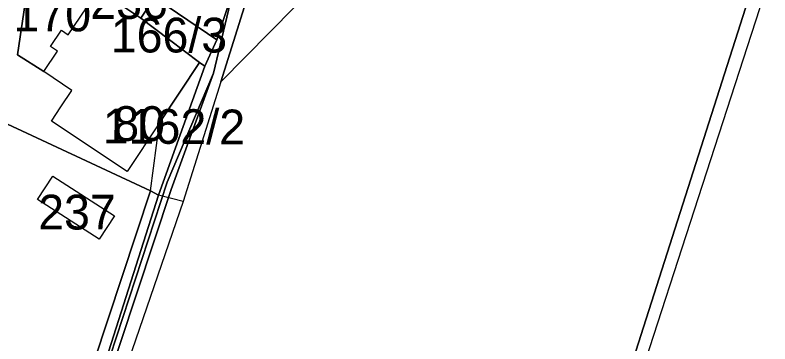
# Model space of a CAD drawing. Extents: x -623250 to -619626, y -1079612 to -1075424.
# Drawn here: x -621418.9 to -621201.9, y -1077758.8 to -1077664.2 of the extents above; entities that cross this region are included whole.
import ezdxf

# ---------------------------------------------------------------- set-up
doc = ezdxf.new("R2010")
doc.units = 0
for name, color, linetype in [('Hranice šetřená (k_ú_Džbánov - vnitřní obvod)', 7, 'Continuous'), ('Parcela nároku', 7, 'Continuous'), ('Parcelní číslo', 7, 'Continuous')]:
    doc.layers.add(name, color=color, linetype=linetype)

msp = doc.modelspace()

# ---------------------------------------------------------------- linework, layer by layer
at = {"layer": 'Hranice šetřená (k_ú_Džbánov - vnitřní obvod)'}
for points in [[(-621379.95, -1077714.81), (-621472.37, -1077671.75), (-621477.29, -1077669.61), (-621474.91, -1077659.48), (-621473.93, -1077656.14), (-621481.28, -1077655.23), (-621493.28, -1077651.08), (-621501.26, -1077644.07), (-621534.26, -1077633.61), (-621575.49, -1077614.16), (-621575.63, -1077614.69), (-621576.66, -1077618.59), (-621578.64, -1077626.08), (-621580.59, -1077633.46), (-621573.12, -1077638.43), (-621578.37, -1077655.91), (-621582.97, -1077675.43), (-621585.55, -1077686.35), (-621591.87, -1077710.12)], [(-621340.28, -1077622.09), (-621346.96, -1077620.27), (-621351.15, -1077650.83), (-621352.43, -1077660.2), (-621359.74, -1077683.39), (-621370.61, -1077717.85), (-621377.7, -1077716.06), (-621379.95, -1077714.81)]]:
    msp.add_lwpolyline(points, dxfattribs=at)
at = {"layer": 'Parcela nároku'}
for points in [[(-621399.07, -1077604.61), (-621366.26, -1077618.67), (-621352.61, -1077624.67), (-621356.07, -1077656.62), (-621360.94, -1077671.33), (-621411.21, -1077637.14)], [(-621287.56, -1077905.65), (-621340.92, -1078060.83), (-621413.47, -1078234.45), (-621461.2, -1078328.4), (-621462.02, -1078334.75), (-621459.02, -1078330.44), (-621410.27, -1078236.51), (-621337.32, -1078062), (-621284.16, -1077906.18), (-621257.6, -1077825.18), (-621204.75, -1077662.32), (-621198.6, -1077626.58), (-621199.7, -1077617.03), (-621206.08, -1077609.32), (-621211.44, -1077608.6), (-621204.6, -1077618.06), (-621201.95, -1077630.34), (-621208.08, -1077659.7), (-621260.76, -1077824.45)], [(-621325.15, -1077626.4), (-621318.07, -1077628.41), (-621297.64, -1077634.23), (-621296.82, -1077634.46), (-621331.45, -1077654.68), (-621359.74, -1077683.39), (-621352.43, -1077660.2), (-621351.15, -1077650.83)], [(-621412.36, -1077639.98), (-621411.21, -1077637.14), (-621360.94, -1077671.33), (-621364.39, -1077678.9), (-621365.89, -1077677.89), (-621374.5, -1077671.38), (-621382.78, -1077665.12), (-621379.74, -1077660.62), (-621391.87, -1077652.44), (-621394.73, -1077656.69), (-621412.76, -1077641.87)], [(-621468.32, -1077652.78), (-621469.02, -1077655.02), (-621472.37, -1077671.75), (-621379.95, -1077714.81), (-621377.39, -1077695.22), (-621386.69, -1077709.23), (-621408.45, -1077694.77), (-621405.71, -1077690.62), (-621402.58, -1077685.89), (-621410.62, -1077680.48), (-621418.22, -1077675.64), (-621414.14, -1077648.39), (-621417.6, -1077642.03), (-621426.47, -1077663.99)], [(-621414.14, -1077648.39), (-621418.22, -1077675.64), (-621410.62, -1077680.48), (-621406.69, -1077674.58), (-621408.69, -1077673.25), (-621405.55, -1077668.55), (-621403.62, -1077669.9), (-621394.73, -1077656.69), (-621412.76, -1077641.87)], [(-621391.87, -1077652.44), (-621379.74, -1077660.62), (-621382.78, -1077665.12), (-621386.75, -1077662.39), (-621394.73, -1077656.69)], [(-621364.39, -1077678.9), (-621360.94, -1077671.33), (-621356.07, -1077656.62), (-621361.81, -1077680.91), (-621375.21, -1077712.24), (-621395.2, -1077773.48), (-621413.63, -1077833.01), (-621448.87, -1077932.09), (-621484.15, -1078031.22), (-621531.47, -1078143.68), (-621559.31, -1078200.97), (-621633.61, -1078348.03), (-621651.3, -1078390.37), (-621666.67, -1078429.48), (-621674.85, -1078456.45), (-621678.32, -1078456.03), (-621652.48, -1078389.36), (-621636.77, -1078350.51), (-621560.48, -1078200.14), (-621532.5, -1078143.13), (-621485.18, -1078030.89), (-621450, -1077931.7), (-621414.98, -1077832.91), (-621377.7, -1077716.06)], [(-621374.5, -1077671.38), (-621365.89, -1077677.89), (-621377.39, -1077695.22), (-621386.69, -1077709.23), (-621408.45, -1077694.77), (-621405.71, -1077690.62), (-621402.58, -1077685.89), (-621410.62, -1077680.48), (-621406.69, -1077674.58), (-621408.69, -1077673.25), (-621405.55, -1077668.55), (-621403.62, -1077669.9), (-621394.73, -1077656.69), (-621386.75, -1077662.39), (-621382.78, -1077665.12)], [(-621379.95, -1077714.81), (-621377.39, -1077695.22), (-621365.89, -1077677.89), (-621364.39, -1077678.9), (-621377.7, -1077716.06)], [(-621394.72, -1077728.71), (-621412.44, -1077717.29), (-621408.03, -1077710.58), (-621390.32, -1077722)], [(-621412.44, -1077717.29), (-621408.03, -1077710.58), (-621390.32, -1077722), (-621394.72, -1077728.71)], [(-621536.14, -1078141.02), (-621489.42, -1078030.25), (-621424.75, -1077849.92), (-621379.95, -1077714.81), (-621377.7, -1077716.06), (-621414.98, -1077832.91), (-621450, -1077931.7), (-621485.18, -1078030.89), (-621532.5, -1078143.13), (-621560.48, -1078200.14), (-621636.77, -1078350.51), (-621652.48, -1078389.36), (-621678.32, -1078456.03), (-621682.14, -1078455.7), (-621640.24, -1078349.18), (-621601.13, -1078271)]]:
    msp.add_lwpolyline(points, close=True, dxfattribs=at)
for points in [[(-621410.27, -1078236.51), (-621337.32, -1078062), (-621284.16, -1077906.18), (-621257.6, -1077825.18), (-621204.75, -1077662.32), (-621198.6, -1077626.58), (-621199.7, -1077617.03), (-621176.54, -1077623.98), (-621168.66, -1077615.74), (-621161.41, -1077628.03), (-621152.23, -1077637.98), (-621149.57, -1077650.51), (-621150.79, -1077666.61), (-621158.39, -1077706.82), (-621163.73, -1077750.52), (-621167.08, -1077794.3), (-621173.84, -1077820.88), (-621199.33, -1077901.86), (-621217.33, -1077958.26), (-621270.05, -1078106.95), (-621312.71, -1078208.01)], [(-621595.12, -1078274.48), (-621557.95, -1078201.7), (-621530.38, -1078144.73), (-621482.76, -1078032.4), (-621447.54, -1077932.95), (-621412.5, -1077833.54), (-621393.67, -1077773.75), (-621374.06, -1077714.41), (-621361.81, -1077680.91), (-621356.07, -1077656.62), (-621352.61, -1077624.67), (-621351.52, -1077619.03), (-621346.96, -1077620.27), (-621351.15, -1077650.83), (-621352.43, -1077660.2), (-621359.74, -1077683.39), (-621370.61, -1077717.85), (-621410.49, -1077834.12), (-621445.17, -1077933.59), (-621480.01, -1078033.01), (-621527.76, -1078145.86), (-621554.92, -1078203.35), (-621592.05, -1078275.81)], [(-621413.47, -1078234.45), (-621340.92, -1078060.83), (-621287.56, -1077905.65), (-621260.76, -1077824.45), (-621208.08, -1077659.7), (-621214.74, -1077657.83), (-621238.69, -1077651.01), (-621258.47, -1077645.38), (-621278, -1077639.82), (-621296.82, -1077634.46), (-621331.45, -1077654.68), (-621359.74, -1077683.39), (-621370.61, -1077717.85), (-621410.49, -1077834.12), (-621445.17, -1077933.59), (-621480.01, -1078033.01), (-621527.76, -1078145.86), (-621554.92, -1078203.35), (-621592.05, -1078275.81)], [(-621706.68, -1078264.18), (-621667.8, -1078192.73), (-621644.39, -1078145.88), (-621611.75, -1078070.36), (-621595.29, -1078022.54), (-621583.38, -1077980.56), (-621575.53, -1077966.39), (-621533.15, -1077847.48), (-621490.7, -1077728.39), (-621473.08, -1077681.08), (-621472.16, -1077677.68), (-621473.46, -1077677.22), (-621472.37, -1077671.75), (-621379.95, -1077714.81), (-621424.75, -1077849.92), (-621489.42, -1078030.25), (-621536.14, -1078141.02), (-621601.13, -1078271)], [(-621633.61, -1078348.03), (-621559.31, -1078200.97), (-621531.47, -1078143.68), (-621484.15, -1078031.22), (-621448.87, -1077932.09), (-621413.63, -1077833.01), (-621395.2, -1077773.48), (-621375.21, -1077712.24), (-621361.81, -1077680.91), (-621374.06, -1077714.41), (-621393.67, -1077773.75), (-621412.5, -1077833.54), (-621447.54, -1077932.95), (-621482.76, -1078032.4), (-621530.38, -1078144.73), (-621557.95, -1078201.7), (-621595.12, -1078274.48)]]:
    msp.add_lwpolyline(points, dxfattribs=at)

# ---------------------------------------------------------------- texts
at = {"layer": 'Parcelní číslo'}
for s, p in [('236', (-621397.28, -1077665.32)), ('170', (-621419.35, -1077668.89)), ('166/3', (-621391.39, -1077674.97)), ('80', (-621390.66, -1077700.42)), ('237', (-621412.26, -1077725.89))]:
    msp.add_text(s, height=10, dxfattribs=at).set_placement(p)
msp.add_text('1162/2', height=10, rotation=359.5194, dxfattribs=at).set_placement((-621393.71, -1077701.09))

doc.saveas('drawing.dxf')
